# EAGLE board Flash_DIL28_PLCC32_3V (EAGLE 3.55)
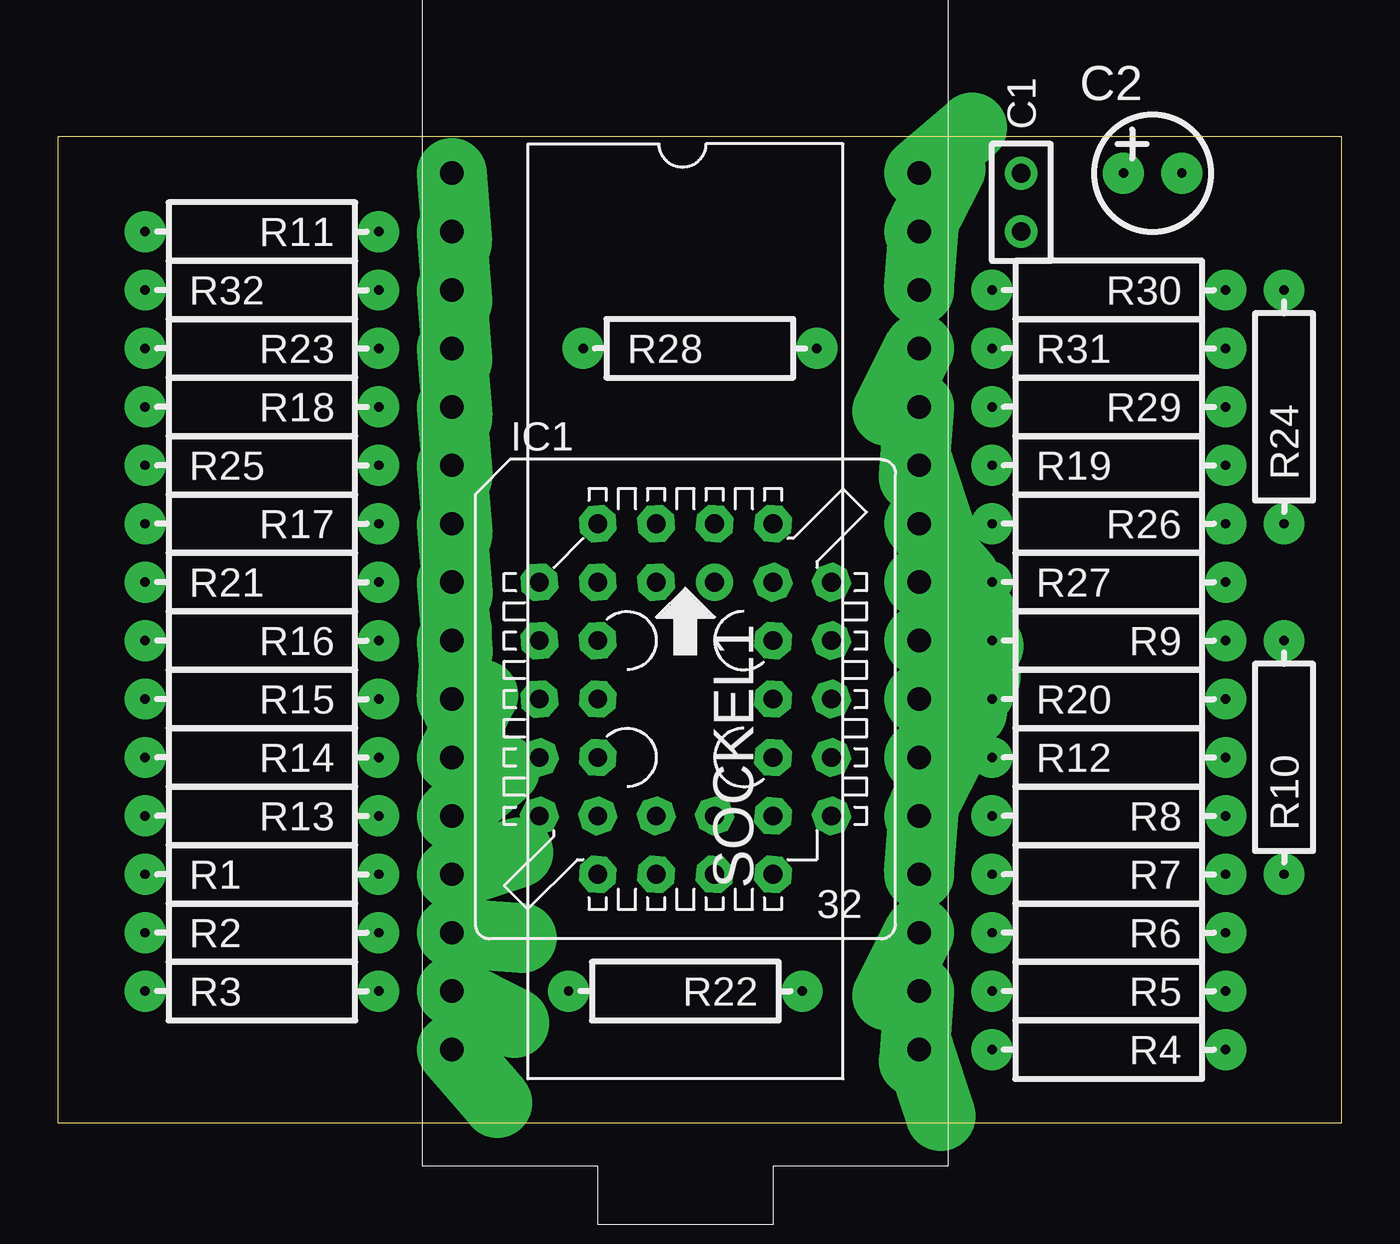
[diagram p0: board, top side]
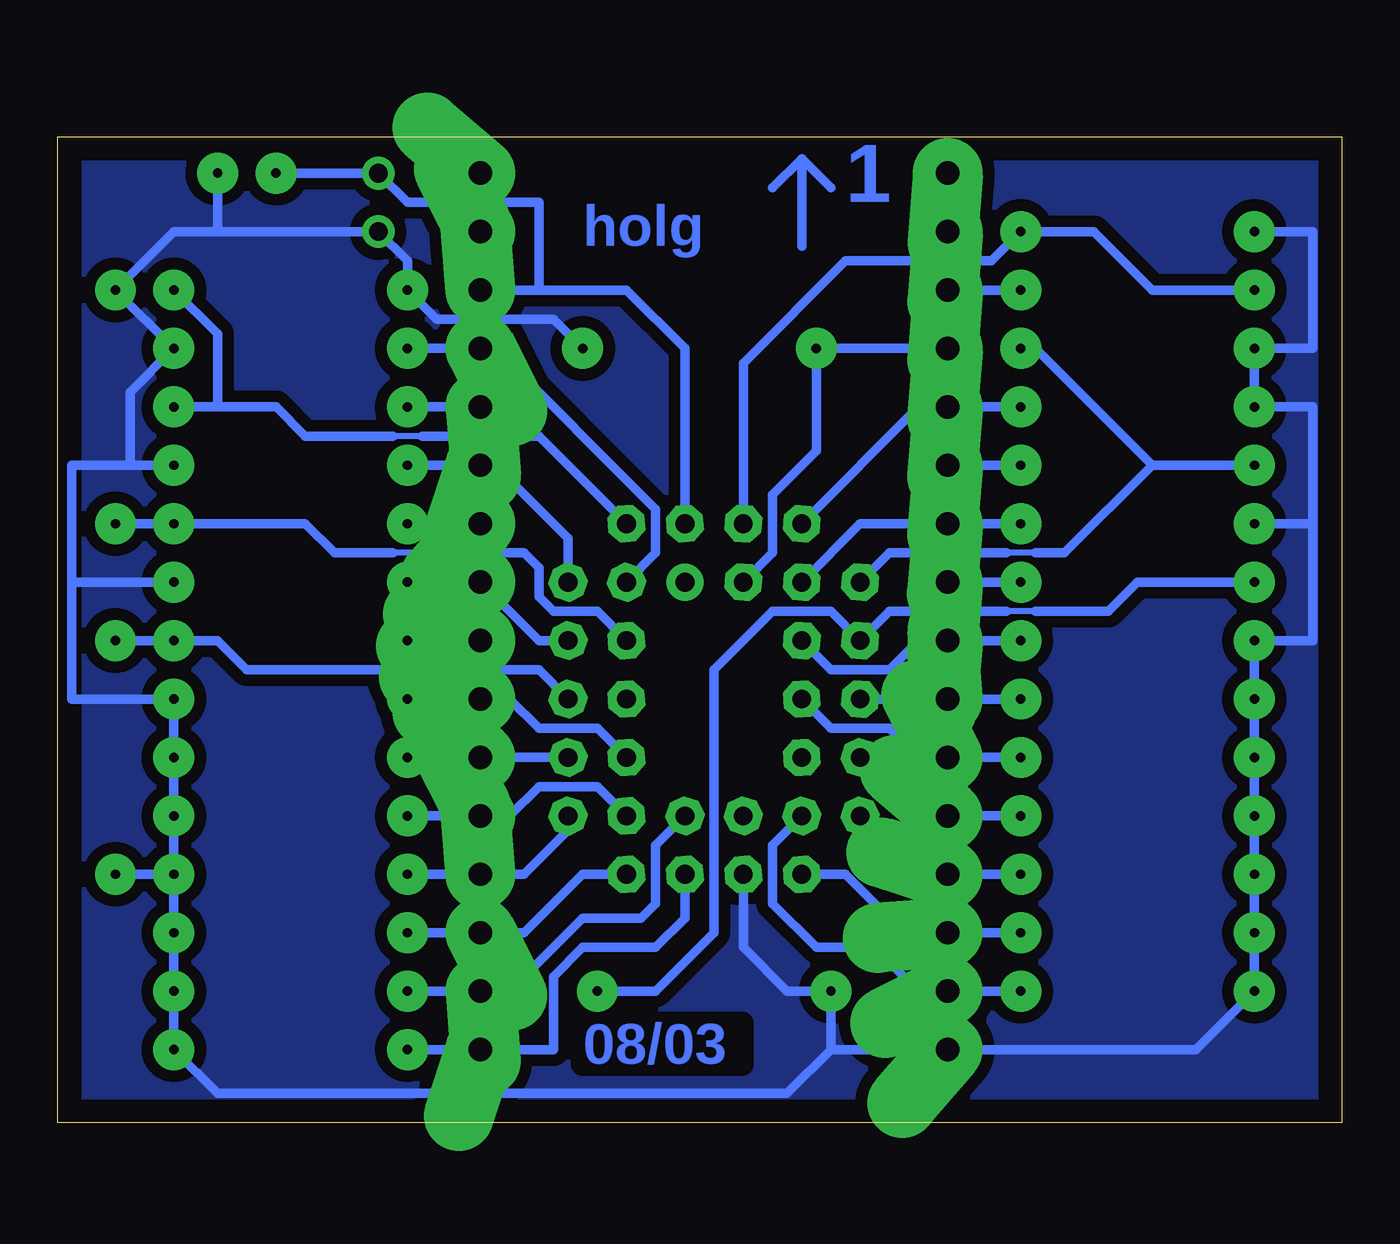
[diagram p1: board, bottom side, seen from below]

Size 55.86 x 42.85 mm. Coordinates in mm from the lower left corner, seen from the top.
Outline: 0,0 55.86,0 55.86,42.85 0,42.85 0,0
Copper layers used: Bottom

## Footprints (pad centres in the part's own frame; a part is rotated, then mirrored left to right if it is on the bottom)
RM2,5 = drill 0.813 pad 1.422 round:  0,0;  2.54,0
KO01 = drill 0.406 pad 1.778 round:  -1.27,0;  1.27,0
C32 = drill 0.813 pad 1.6 round:  1.27,5.08 | drill 0.813 pad 1.6 octagon:  -1.27,7.62;  -1.27,5.08;  -3.81,7.62;  -6.35,5.08;  -3.81,5.08;  -6.35,2.54;  -3.81,2.54;  -6.35,0;  -3.81,0;  -6.35,-2.54;  -3.81,-2.54;  -6.35,-5.08;  -3.81,-7.62;  -3.81,-5.08;  -1.27,-7.62;  -1.27,-5.08;  1.27,-7.62;  1.27,-5.08;  3.81,-7.62;  6.35,-5.08;  3.81,-5.08;  6.35,-2.54;  3.81,-2.54;  6.35,0;  3.81,0;  6.35,2.54;  3.81,2.54;  6.35,5.08;  3.81,7.62;  3.81,5.08;  1.27,7.62
S04 = drill 0.406 pad 1.778 round:  -5.08,0;  5.08,0
AOV32 = drill 1.016 pad 3.048 offset:  -19.05,-10.16;  -16.51,-10.16;  -3.81,-10.16;  -1.27,-10.16;  -13.97,-10.16;  -11.43,-10.16;  -6.35,-10.16;  -8.89,-10.16;  1.27,-10.16;  3.81,-10.16;  6.35,-10.16;  8.89,-10.16;  11.43,-10.16;  13.97,-10.16;  16.51,-10.16;  19.05,-10.16;  19.05,10.16;  16.51,10.16;  13.97,10.16;  11.43,10.16;  8.89,10.16;  6.35,10.16;  3.81,10.16;  1.27,10.16;  -1.27,10.16;  -3.81,10.16;  -6.35,10.16;  -8.89,10.16;  -11.43,10.16;  -13.97,10.16;  -16.51,10.16;  -19.05,10.16

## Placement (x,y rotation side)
C1  C100NK  [RM2,5]  41.91,38.73 90 top
C2  4u7  [KO01]  47.62,41.27 0 top
IC1  27LV256  [C32]  27.3,18.41 0 top
R1  5k6  [S04]  8.89,10.79 0 top
R2  5k6  [S04]  8.89,8.26 0 top
R3  5k6  [S04]  8.89,5.71 0 top
R4  5k6  [S04]  45.72,3.17 180 top
R5  5k6  [S04]  45.72,5.71 180 top
R6  5k6  [S04]  45.72,8.26 180 top
R7  5k6  [S04]  45.72,10.79 180 top
R8  5k6  [S04]  45.72,13.34 180 top
R9  3k3  [S04]  45.72,20.95 180 top
R10  10k  [S04]  53.34,15.88 90 top
R11  10k  [S04]  8.89,38.73 180 top
R12  2k7  [S04]  45.72,15.88 0 top
R13  2k7  [S04]  8.89,13.34 180 top
R14  2k7  [S04]  8.89,15.88 180 top
R15  2k7  [S04]  8.89,18.41 180 top
R16  2k7  [S04]  8.89,20.95 180 top
R17  2k7  [S04]  8.89,26.04 180 top
R18  2k7  [S04]  8.89,31.11 180 top
R19  2k7  [S04]  45.72,28.57 0 top
R20  2k7  [S04]  45.72,18.41 0 top
R21  3k3  [S04]  8.89,23.5 0 top
R22  10k  [S04]  27.3,5.71 180 top
R23  10k  [S04]  8.89,33.66 180 top
R24  10k  [S04]  53.34,31.11 90 top
R25  3k3  [S04]  8.89,28.57 0 top
R26  3k3  [S04]  45.72,26.04 180 top
R27  2k7  [S04]  45.72,23.5 0 top
R28  2k7  [S04]  27.94,33.66 0 top
R29  3k3  [S04]  45.72,31.11 180 top
R30  10k  [S04]  45.72,36.2 180 top
R31  2k7  [S04]  45.72,33.66 0 top
R32  3k3  [S04]  8.89,36.2 0 top
SOCKEL1  Sockel1  [AOV32]  27.3,22.23 270 top

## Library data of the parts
C1 = holgnorm
C2 R1-R32 = holg_plt
IC1 = ic_holg
SOCKEL1 = galeprom

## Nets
/CE: IC1. R12. SOCKEL1.
/OE: R9. SOCKEL1.
/WR: R32. SOCKEL1.
/WRB: IC1. R11. R32.
A0: IC1. R13. SOCKEL1.
A1: IC1. R14. SOCKEL1.
A2: IC1. R15. SOCKEL1.
A3: IC1. R16. SOCKEL1.
A4: R21. SOCKEL1.
A4B: IC1. R21. R22.
A5: IC1. R17. SOCKEL1.
A6: R25. SOCKEL1.
A6B: IC1. R23. R25.
A7: IC1. R18. SOCKEL1.
A8: IC1. R19. SOCKEL1.
A9: R26. SOCKEL1.
A9B: IC1. R24. R26.
A10: IC1. R20. SOCKEL1.
A11: IC1. R27. SOCKEL1.
A12: IC1. R28. SOCKEL1.
A13: R29. SOCKEL1.
A13B: IC1. R29. R30.
A14: IC1. R31. SOCKEL1.
D0: IC1. R1. SOCKEL1.
D1: IC1. R2. SOCKEL1.
D2: IC1. R3. SOCKEL1.
D3: IC1. R4. SOCKEL1.
D4: IC1. R5. SOCKEL1.
D5: IC1. R6. SOCKEL1.
D6: IC1. R7. SOCKEL1.
D7: IC1. R8. SOCKEL1.
GND: C1. C2. IC1. R1. R2. R3. R4. R5. R6. R7. R8. R10. R11. R12. R13. R14. R15. R16. R17. R18. R19. R20. R22. R23. R24. R27. R28. R30. R31. SOCKEL1.
N$3: C1. C2. IC1. SOCKEL1.
N$5: IC1. R9. R10.

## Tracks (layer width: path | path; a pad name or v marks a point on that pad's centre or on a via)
/CE
  Bottom 0.406: 40.64,15.88 37.47,15.88 33.66,15.88
/OE
  Bottom 0.406: 37.47,20.95 R9.
/WR
  Bottom 0.406: R32. 17.14,36.2
/WRB
  Bottom 0.406: 26.04,26.04 26.04,33.02 21.59,37.47 15.24,37.47 13.97,38.73 10.79,38.73 8.26,36.2 3.81,36.2
A0
  Bottom 0.406: 13.97,13.34 17.14,13.34 18.41,13.34 20.95,15.88
A1
  Bottom 0.406: 13.97,15.88 17.14,15.88 18.41,15.88 19.68,17.14 22.23,17.14 23.5,18.41
A2
  Bottom 0.406: 13.97,18.41 17.14,18.41 20.95,18.41
A3
  Bottom 0.406: 13.97,20.95 17.14,20.95 18.41,20.95 19.68,19.68 22.23,19.68 23.5,20.95
A4
  Bottom 0.406: R21. 17.14,23.5
A4B
  Bottom 0.254: 13.34,22.23 14.61,22.23
  Bottom 0.406: 32.38,5.71 29.84,5.71 27.3,8.26 27.3,19.68 24.77,22.23 22.23,22.23 20.95,20.95 19.68,22.23 14.61,22.23 | 3.81,23.5 8.89,23.5 10.16,22.23 13.34,22.23
A5
  Bottom 0.406: 13.97,26.04 17.14,26.04 20.95,26.04 23.5,23.5
A6
  Bottom 0.406: R25. 17.14,28.57
A6B
  Bottom 0.254: 13.34,24.77 14.61,24.77
  Bottom 0.406: 3.81,28.57 8.26,28.57 | 8.26,28.57 13.34,33.66 13.97,33.66 | 20.95,23.5 19.68,24.77 14.61,24.77 | 13.34,24.77 12.06,24.77 8.26,28.57
A7
  Bottom 0.406: 13.97,31.11 17.14,31.11 18.41,31.11 23.5,26.04
A8
  Bottom 0.406: 40.64,28.57 37.47,28.57 36.83,28.57 33.66,25.4 33.66,23.5
A9
  Bottom 0.406: 37.47,26.04 R26.
A9B
  Bottom 0.254: 40.01,24.77 41.27,24.77
  Bottom 0.406: 53.34,26.04 50.8,26.04 45.09,26.04 43.81,24.77 41.27,24.77 | 31.11,20.95 32.38,22.23 34.29,22.23 34.92,22.86 34.92,24.13 35.56,24.77 40.01,24.77
A10
  Bottom 0.406: 37.47,18.41 40.64,18.41 37.47,18.41 | 31.11,15.88 32.38,17.14 34.92,17.14 36.2,18.41 37.47,18.41
A11
  Bottom 0.406: 40.64,23.5 37.47,23.5 34.92,20.95 33.66,20.95
A12
  Bottom 0.406: 17.14,33.66 22.86,33.66 22.86,29.21 24.77,27.3 24.77,24.77 26.04,23.5
A13
  Bottom 0.406: 37.47,31.11 R29.
A13B
  Bottom 0.254: 40.01,29.84 41.27,29.84
  Bottom 0.406: 31.11,26.04 34.92,29.84 40.01,29.84 | 48.9,31.11 46.35,31.11 45.09,29.84 41.27,29.84 | 48.9,31.11 50.8,31.11 | 50.8,36.2 48.9,34.29 48.9,31.11
A14
  Bottom 0.406: 40.64,33.66 37.47,33.66 36.83,33.66 29.84,26.67 29.84,24.77 31.11,23.5
D0
  Bottom 0.406: R1. 17.14,10.79 18.41,10.79 20.95,13.34
D1
  Bottom 0.406: R2. 17.14,8.26 19.05,8.26 21.59,10.79 23.5,10.79
D2
  Bottom 0.406: R3. 17.14,5.71 18.41,5.71 20.32,7.62 22.86,7.62 24.77,9.53 24.77,12.06 23.5,13.34
D3
  Bottom 0.406: R4. 37.47,3.17 34.29,3.17 34.29,6.35 33.02,7.62 29.84,7.62 28.57,8.89 28.57,10.79
D4
  Bottom 0.406: R5. 37.47,5.71 36.2,5.71 33.02,8.89 30.48,8.89 29.84,9.53 29.84,12.06 28.57,13.34
D5
  Bottom 0.406: R6. 37.47,8.26 35.56,8.26 33.02,10.79 31.11,10.79
D6
  Bottom 0.406: R7. 37.47,10.79 35.56,10.79 33.66,12.7 33.66,13.34
D7
  Bottom 0.406: R8. 37.47,13.34 36.2,13.34 34.92,14.61 32.38,14.61 31.11,13.34
GND
  Bottom 0.406: 1.27,26.04 1.27,31.11 R18. R23. 1.27,33.66 1.27,38.73 R11. | 1.27,26.04 R17. | 22.23,3.17 17.14,3.17 6.35,3.17 3.81,5.71 3.81,8.26 3.81,10.79 R13. R14. R15. R16. 1.27,20.95 1.27,26.04 | 22.23,3.17 24.13,1.27 48.9,1.27 50.8,3.17 50.8,5.71 50.8,8.26 50.8,10.79 | 50.8,10.79 50.8,13.34 R12. R20. 55.24,18.41 55.24,23.5 | 48.9,38.73 C2. | 22.23,3.17 R22. 24.13,5.71 26.04,7.62 26.04,10.79 | R28. 34.29,34.92 39.37,34.92 R30. 40.64,37.47 41.91,38.73 48.9,38.73 | 48.9,38.73 50.8,38.73 R24. R31. 52.7,31.75 52.7,28.57 | 50.8,10.79 53.34,10.79 | 55.24,23.5 R27. | 52.7,28.57 R19. | 52.7,28.57 55.24,28.57 55.24,23.5
  pour Bottom (isolate 0.508): 0.64,41.91 0.64,0.64 55.24,0.64 55.24,41.91
N$2
  Bottom 0.406: 23.5,41.91 23.5,38.1 | 23.5,41.91 24.77,40.64 | 22.23,40.64 23.5,41.91
N$3
  Bottom 0.406: 46.35,41.27 C1. 40.64,40.01 34.92,40.01 34.92,36.2 | IC1. 28.57,33.66 31.11,36.2 34.92,36.2 | 34.92,36.2 37.47,36.2
N$5
  Bottom 0.254: 40.01,19.68 41.27,19.68
  Bottom 0.406: 33.66,18.41 34.92,19.68 40.01,19.68 | 41.27,19.68 47.62,19.68 48.9,20.95 50.8,20.95 R10.

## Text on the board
Bottom: 1 | holg | 08/03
